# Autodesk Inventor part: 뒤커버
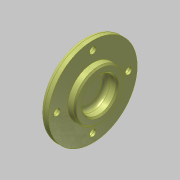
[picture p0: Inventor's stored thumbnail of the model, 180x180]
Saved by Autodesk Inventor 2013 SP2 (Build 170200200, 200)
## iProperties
Created: 2015-12
Part Number: 뒤커버
Document SubType Name: Modeling
Designer: mdu
Density: 2.71 g/cm^3
Material: 알루미늄 6061
Mass: 56.2007 g
Surface Area: 84.0408 cm^2
Volume: 20.7383 cm^3
Author: mdu
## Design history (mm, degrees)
sketch "스케치1"
  geometry: L1 (-7, 0)-(7, 0); L2 (-7, 0)-(-7, 15.539); L3 (-7, 15.539)-(-4, 18.5); L4 (-4, 18.5)-(-4, 31); L5 (-4, 31)-(2, 31); L6 (2, 31)-(2, 17.5); L7 (2, 17.5)-(7, 17.5); L8 (7, 17.5)-(7, 0); 2 further points
  constraints: 16 end point, 4 parallel, 2 perpendicular, 1 coincident, 1 horizontal, 1 midpoint
  dimensions: "d0" = 14 distance of L1.start L1.end; "d1" = 62 diameter of L5 L1; "d2" = 35 diameter of L7 L1; "d3" = 37 diameter of L3.end L1; "d4" = 3 distance between parallel lines of L4 L2; "d5" = 6 distance of L4.end L5.end
revolve "회전1" sketch "스케치1" stored, may be unused: angle "d6" = 90 deg
sketch "스케치2" dims "d32" = 50
  geometry: 3 further points
  constraints: 2 vertical alignment, 1 coincident, 2 other
hole "구멍1" sketch "스케치2" at (0, 25) diameter "d8" = 4.5; stored, may be unused: countersink angle "d12" = 90 deg, drill point angle "d14" = 118 deg; dims "d9" = 6, "d10" = 8, "d11" = 4.4, "d13" = 8
hole "구멍2" diameter "d20" = 24; stored, may be unused: countersink angle "d24" = 90 deg, drill point angle "d26" = 0 deg; dims "d18" = 10, "d19" = 10, "d21" = 6, "d22" = 8, "d23" = 4.4, "d25" = 8
fillet "모깎기1" dims "d27" = 3
fillet "모깎기2" dims "d28" = 3
chamfer "모따기1" distance "d29" = 1; stored, may be unused: second distance "d30" = 2, angle "d31" = 45 deg
node "솔리드1"
pattern_circular "원형 패턴1" dims angle "d16" = 360 deg
